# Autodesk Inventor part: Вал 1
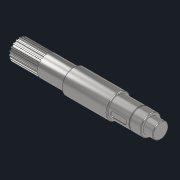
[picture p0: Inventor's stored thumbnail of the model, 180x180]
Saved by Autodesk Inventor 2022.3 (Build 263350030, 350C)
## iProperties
Created: 2022-08
Part Number: Вал 1
Material: Сталь 40ХНМА
Document SubType Name: Modeling
Designer: Карташов
Density: 7.85 g/cm^3
Appearance: С умеренной полировкой
Author: Карташов
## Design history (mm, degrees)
sketch "Эскиз1"
  geometry: L1 (0, 0)-(-855.567, 0); L2 (0, 0)-(0, 30); L3 (0, 30)-(-38, 30); L4 (-38, 30)-(-38, 40); L5 (-38, 40)-(-80, 40); L6 (-80, 40)-(-80, 38.25); L7 (-80, 38.25)-(-84, 38.25); L8 (-84, 38.25)-(-84, 40); L9 (-84, 40)-(-164, 40); L10 (-164, 40)-(-164, 40); L11 (-164, 40)-(-164, 47); L12 (-164, 47)-(-338, 47); L13 (-338, 47)-(-338, 40); L14 (-338, 40)-(-550, 40); L15 (-550, 40)-(-550, 0); 4 further points
  constraints: 32 end point, 5 vertical, 4 horizontal, 3 midpoint, 3 parallel, 3 perpendicular, 2 horizontal alignment, 1 point on line
  dimensions: "d0" = 60 diameter of L3 L1; "d1" = 80 diameter of L5 point (-427.784, 0); "d2" = 76.5 diameter of L7 L1; "d3" = 94 diameter of L12 L1; "d4" = 80 diameter of L14 L1; "d5" = 550 distance between parallel lines of L15 L2; "d6" = 126 horizontal distance of point (-164, 43.5) point (-38, 35); "d7" = 212 distance of L13.end L14.end; "d8" = 174 distance of L11.end L12.end; "d27" = 80 distance from line of L11 L8.end; "d28" = 4 distance of L6.end L7.end
revolve "Вращение1" sketch "Эскиз1" stored, may be unused: angle "d9" = 90 deg
sketch "Эскиз2" dims "d10" = 72
  geometry: L1 (-2, 35.944)-(2, 35.944); L2 (2, 35.944)-(2, 39.95); L3 (-2, 39.95)-(-2, 35.944); L4 (-9.205, 34.803)-(-10.443, 38.613); L5 (-14.247, 37.377)-(-13.01, 33.567); L6 (-19.51, 30.255)-(-21.864, 33.496); L7 (-25.1, 31.145)-(-22.746, 27.904); L8 (-27.904, 22.746)-(-31.145, 25.1); L9 (-33.496, 21.864)-(-30.255, 19.51); L10 (-33.567, 13.01)-(-37.377, 14.247); L11 (-38.613, 10.443)-(-34.803, 9.205); L12 (-35.944, 2)-(-39.95, 2); L13 (-39.95, -2)-(-35.944, -2); L14 (-34.803, -9.205)-(-38.613, -10.443); L15 (-37.377, -14.247)-(-33.567, -13.01); L16 (-30.255, -19.51)-(-33.496, -21.864); L17 (-31.145, -25.1)-(-27.904, -22.746); L18 (-22.746, -27.904)-(-25.1, -31.145); L19 (-21.864, -33.496)-(-19.51, -30.255); L20 (-13.01, -33.567)-(-14.247, -37.377); L21 (-10.443, -38.613)-(-9.205, -34.803); L22 (-2, -35.944)-(-2, -39.95); L23 (2, -39.95)-(2, -35.944); L24 (9.205, -34.803)-(10.443, -38.613); L25 (14.247, -37.377)-(13.01, -33.567); L26 (19.51, -30.255)-(21.864, -33.496); L27 (25.1, -31.145)-(22.746, -27.904); L28 (27.904, -22.746)-(31.145, -25.1); L29 (33.496, -21.864)-(30.255, -19.51); L30 (33.567, -13.01)-(37.377, -14.247); L31 (38.613, -10.443)-(34.803, -9.205); L32 (35.944, -2)-(39.95, -2); L33 (39.95, 2)-(35.944, 2); L34 (34.803, 9.205)-(38.613, 10.443); L35 (37.377, 14.247)-(33.567, 13.01); L36 (30.255, 19.51)-(33.496, 21.864); L37 (31.145, 25.1)-(27.904, 22.746); L38 (22.746, 27.904)-(25.1, 31.145); L39 (21.864, 33.496)-(19.51, 30.255); L40 (13.01, 33.567)-(14.247, 37.377); L41 (10.443, 38.613)-(9.205, 34.803); C1 r 40 at (0, 0) reference; 8 further points
  constraints: 82 end point, 1 coincident, 1 horizontal, 1 parallel, 1 perpendicular, 1 vertical alignment, 126 other
  dimensions: "d11" = 4 distance of L2.end L3.start; "d14" = 360 deg dimension on point (0, 0) L1.end (derived)
extrude "Выдавливание1" cut sketch "Эскиз2" distance "d16" = 110; taper "d17" = 0 deg
chamfer "Фаска1" distance "d21" = 2; stored, may be unused: second distance "d22" = 2, angle "d23" = 45 deg
node "РабПлоскость1"
sketch "Эскиз3"
  geometry: L1 (-20.5, 0)-(20.5, 0); L2 (-20.5, -11)-(20.5, -11); L3 (20.5, 11)-(-20.5, 11); L4 (-40, 45)-(-40, -45) reference; A1 r 11 centre (-20.5, 0) between (-20.5, 11) and (-20.5, -11); A2 r 11 centre (20.5, 0) between (20.5, -11) and (20.5, 11); 3 further points
  constraints: 8 end point, 4 point on circle, 4 tangent, 2 centre point, 2 midpoint, 1 horizontal, 1 horizontal alignment, 1 parallel
  dimensions: "d24" = 41 distance of L1.start L1.end; "d25" = 22 diameter of A2; "d26" = 19.5 distance from line of L1.start L4
extrude "Выдавливание2" cut sketch "Эскиз3" distance "d29" = 4.4; taper "d30" = 0 deg
node "Твердое тело1"
pattern_circular "Круговой массив1" dims angle "d19" = 360 deg
node "Спроецированная петля1"
